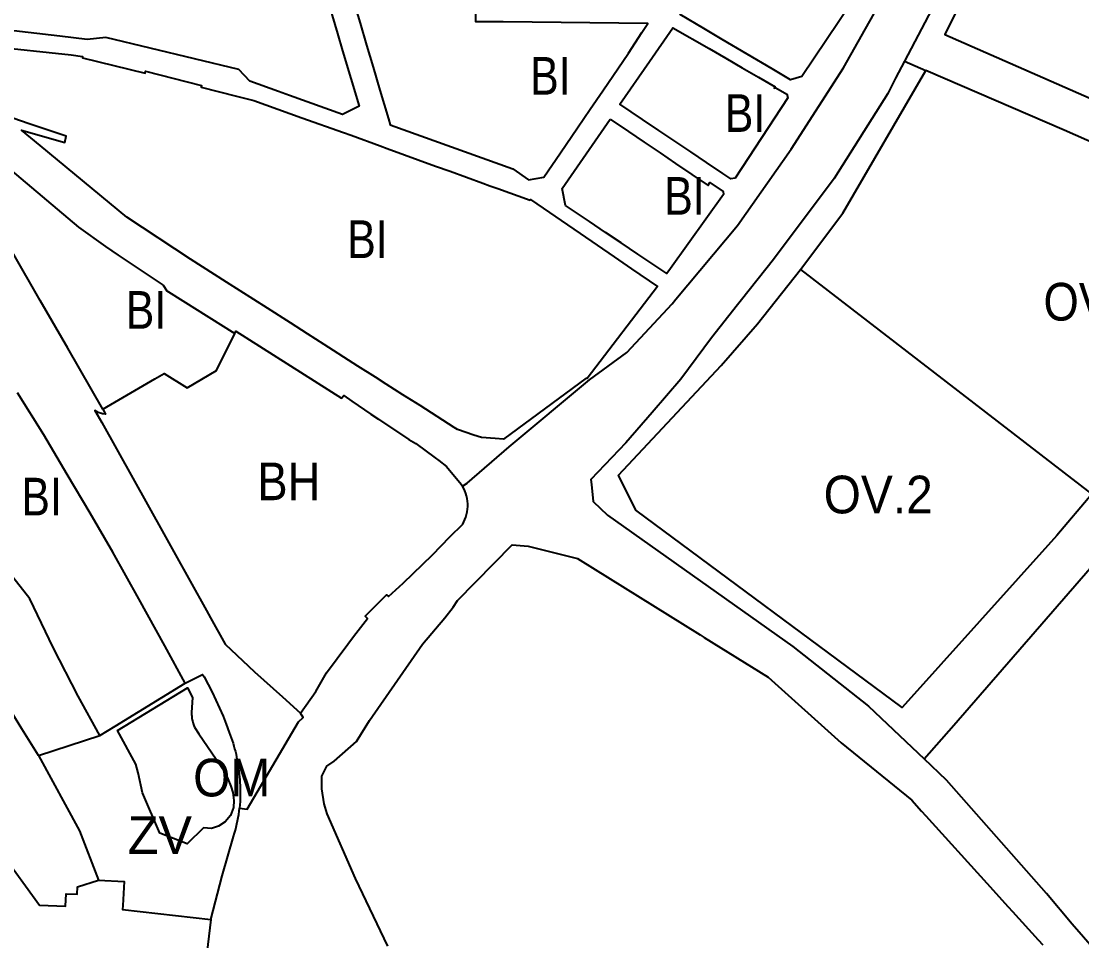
# Model space of a CAD drawing. Extents: x -650451 to -642268, y -1075216 to -1066610.
# Drawn here: x -646568.6 to -646146.5, y -1071706.5 to -1071340.4 of the extents above; entities that cross this region are included whole.
import ezdxf

# ---------------------------------------------------------------- set-up
doc = ezdxf.new("R2010")
doc.units = 0
doc.header["$LTSCALE"] = 6
doc.layers.add('1', color=7, linetype='Continuous', lineweight=35)
doc.layers.add('2', color=7, linetype='Continuous')
doc.layers.add('3', color=7, linetype='Continuous')

msp = doc.modelspace()

# ---------------------------------------------------------------- linework, layer by layer
at = {"layer": '1'}
for p, q in [((-646217.049, -1071356.382), (-646208.577, -1071360.044)), ((-646258.487, -1071439.265), (-646142.584, -1071528.664)), ((-646561.68, -1071632.65), (-646537.28, -1071624.8))]:
    msp.add_line(p, q, dxfattribs=at)
for points in [[(-646392.911, -1071525.561), (-646391.108, -1071524.244), (-646374.45, -1071509.81), (-646342.45, -1071483.12), (-646327.57, -1071472.32), (-646309.6, -1071452.95), (-646308.03, -1071451.08), (-646283.51, -1071421.76), (-646262.18, -1071391.43), (-646241.36, -1071358.97), (-646222.12, -1071324.74), (-646206.54, -1071289.65), (-646193.19, -1071252.61), (-646178.49, -1071182.4), (-646171.94, -1071170.27), (-646172.61, -1071166.36), (-646173.64, -1071160.29), (-646173.49, -1071159.23), (-646173.32, -1071157.96), (-646170.85, -1071151.93)], [(-646063.59, -1071186.331), (-646067.78, -1071184.93), (-646098.16, -1071177.77), (-646109.85, -1071175.02), (-646126.02, -1071172.86), (-646132.63, -1071174.42), (-646136.02, -1071175.37), (-646145.65, -1071182.37), (-646154.59, -1071201.81), (-646173.21, -1071258.81), (-646188.04, -1071296.73), (-646204.83, -1071333.12), (-646217.049, -1071356.382)], [(-646067.097, -1071196.699), (-646132.307, -1071183.438), (-646143.982, -1071201.827), (-646151.834, -1071223.174), (-646162.478, -1071257.888), (-646165.996, -1071267.807), (-646186.109, -1071315.352), (-646201.064, -1071345.678), (-646127.301, -1071378.036)], [(-646452.25, -1071312.89), (-646442.68, -1071345.32), (-646440.65, -1071352.19), (-646434.14, -1071374.25), (-646440.74, -1071377.55), (-646461.86, -1071369.97), (-646466.24, -1071368.39), (-646477.53, -1071364.34), (-646481.95, -1071359.59), (-646517.19, -1071351.18), (-646534.95, -1071346.94), (-646542.32, -1071347.73), (-646553.24, -1071346.43), (-646574.89, -1071343.86)], [(-646439.12, -1071323.11), (-646433.72, -1071341.27), (-646431.13, -1071350.01), (-646428.54, -1071358.71), (-646425.8, -1071367.9), (-646422.43, -1071379.23), (-646421.72, -1071381.63), (-646372.95, -1071399.22), (-646366.71, -1071403.61), (-646360.58, -1071402.51), (-646353.92, -1071392.76), (-646347.17, -1071382.87), (-646342.11, -1071375.46), (-646337.08, -1071368.1), (-646326.88, -1071353.16), (-646321.55, -1071344.91), (-646319.22, -1071341.3), (-646376.74, -1071340.72), (-646387.69, -1071340.72), (-646387.69, -1071331.92)], [(-646581.25, -1071350.31), (-646548.68, -1071353.85), (-646544.12, -1071354.44), (-646544.23, -1071354.96), (-646519.26, -1071361.18), (-646519.06, -1071360.35), (-646496.85, -1071366.04), (-646497.01, -1071366.72), (-646482.94, -1071370.22), (-646475.95, -1071372.05), (-646456.84, -1071378.89), (-646440.29, -1071384.76), (-646437.31, -1071385.84), (-646425.79, -1071390.03), (-646422.97, -1071391.05), (-646403.65, -1071398.07), (-646397.82, -1071400.18), (-646384.85, -1071404.89), (-646382.03, -1071405.91), (-646378.93, -1071407.04), (-646366.05, -1071411.72), (-646365.93, -1071411.37), (-646346.14, -1071424.95), (-646339.37, -1071429.58), (-646332.59, -1071434.24), (-646325.72, -1071438.95), (-646315.42, -1071446.02), (-646343.41, -1071482.71), (-646343.74, -1071482.57), (-646376.59, -1071506.83), (-646379.94, -1071506.59), (-646385.46, -1071506.19), (-646388.5, -1071505.15), (-646394.92, -1071502.97), (-646396.23, -1071502.14), (-646403.11, -1071497.75), (-646409.86, -1071493.44), (-646416.64, -1071489.13), (-646423.34, -1071484.85), (-646427.63, -1071482.12), (-646434.56, -1071477.7), (-646448, -1071469.14), (-646454.64, -1071464.89), (-646461.44, -1071460.52), (-646470.57, -1071454.67), (-646486.82, -1071444.25), (-646501.13, -1071435.17), (-646526.53, -1071418.41), (-646561.07, -1071389.85), (-646568.41, -1071383.81), (-646551.23, -1071388.71), (-646550.7, -1071386.17), (-646565.84, -1071381.21), (-646571.49, -1071379.19)], [(-646217.049, -1071356.382), (-646220.61, -1071363.16), (-646223.77, -1071369.24), (-646245.1, -1071403.04), (-646269.2, -1071435.22), (-646281.99, -1071451.4), (-646283.52, -1071453.34), (-646293.87, -1071466.43), (-646306.14, -1071482.86), (-646317.52, -1071496.12), (-646327.97, -1071508.29), (-646341.88, -1071522.81), (-646341.66, -1071524.87), (-646340.93, -1071531.64), (-646335.3, -1071537.05), (-646261.46, -1071589.38), (-646231.43, -1071613.06), (-646223.928, -1071620.168), (-646209.322, -1071634.004)], [(-646258.487, -1071439.265), (-646241.68, -1071416.887), (-646208.577, -1071360.044)], [(-646132.229, -1071393.179), (-646153.5, -1071383.85), (-646208.577, -1071360.044)], [(-646536.06, -1071494.9), (-646550.03, -1071470.64), (-646561, -1071451.57), (-646593.69, -1071394.81), (-646587.53, -1071387.19), (-646572.96, -1071399.49), (-646545.77, -1071422.43), (-646535.05, -1071430.14), (-646529.94, -1071433.53), (-646512.01, -1071445.44), (-646510.63, -1071447.76), (-646509.94, -1071448.19), (-646504.28, -1071451.75), (-646483.58, -1071464.76)], [(-646209.322, -1071634.004), (-646197.398, -1071620.579), (-646077.593, -1071482.499), (-646044.949, -1071425.333)], [(-646142.584, -1071528.664), (-646156.471, -1071545.166), (-646217.978, -1071613.552), (-646324, -1071535), (-646330.914, -1071521.11), (-646289.976, -1071477.514), (-646275.615, -1071460.886), (-646258.487, -1071439.265)], [(-646536.06, -1071494.9), (-646515.35, -1071482.75), (-646511.72, -1071480.63), (-646502.58, -1071486.42), (-646490.89, -1071479.44), (-646483.58, -1071464.76)], [(-646483.58, -1071464.76), (-646483.107, -1071463.81), (-646441.14, -1071490.5), (-646440.16, -1071489.43), (-646437.01, -1071491.61), (-646429.42, -1071496.8), (-646426.43, -1071498.81), (-646414.36, -1071506.9), (-646411.47, -1071508.58), (-646403.78, -1071514.21), (-646402.38, -1071515.24), (-646399.37, -1071517.73), (-646393.44, -1071524.71), (-646392.911, -1071525.561)], [(-646503.31, -1071603.95), (-646511.47, -1071589.11), (-646521.8, -1071570.34), (-646532.04, -1071551.72), (-646541.14, -1071536.3), (-646550.23, -1071520.88), (-646559.53, -1071505.12), (-646570, -1071488.38)], [(-646536.06, -1071494.9), (-646535.08, -1071496.91), (-646536.26, -1071496.69), (-646537.89, -1071496.17), (-646539.23, -1071495.37), (-646536.45, -1071500.22), (-646511.87, -1071544.47), (-646507.87, -1071551.64), (-646494.85, -1071575.01), (-646493.27, -1071577.93), (-646487.37, -1071588.37), (-646478.18, -1071597.11), (-646475.69, -1071599.42), (-646464.59, -1071609.41), (-646457.49, -1071615.83)], [(-646537.28, -1071624.8), (-646545.89, -1071609.07), (-646555.78, -1071589.66), (-646565.17, -1071570.4), (-646598.63, -1071527.8), (-646609.21, -1071510.98)], [(-646457.49, -1071615.83), (-646451.35, -1071607.3), (-646447.13, -1071599.81), (-646438.62, -1071588.36), (-646436.34, -1071585.29), (-646430.71, -1071578.12), (-646431.67, -1071577.22), (-646423.17, -1071568.77), (-646422.45, -1071569.38), (-646416.52, -1071564.16), (-646404.87, -1071552.83), (-646397.94, -1071545.68), (-646392.89, -1071540.59), (-646392.421, -1071539.705), (-646392.006, -1071538.774), (-646391.649, -1071537.804), (-646391.357, -1071536.799), (-646391.134, -1071535.766), (-646390.982, -1071534.712), (-646390.905, -1071533.645), (-646390.904, -1071532.572), (-646390.979, -1071531.502), (-646391.13, -1071530.442), (-646391.354, -1071529.401), (-646391.649, -1071528.386), (-646392.01, -1071527.404), (-646392.432, -1071526.46), (-646392.911, -1071525.561)], [(-646422.74, -1071708.61), (-646435.53, -1071681.73), (-646446.848, -1071655.933), (-646448, -1071652), (-646449, -1071646), (-646449, -1071641), (-646447, -1071637), (-646444, -1071635), (-646435.08, -1071627.07), (-646429.99, -1071618.76), (-646408.82, -1071588.44), (-646399.95, -1071577.85), (-646396.74, -1071573.64), (-646395.01, -1071571.03), (-646373.15, -1071548.85), (-646366.81, -1071549.42), (-646347.22, -1071554.23), (-646298.46, -1071584.67), (-646296.79, -1071585.71), (-646271.38, -1071601.57), (-646242.35, -1071627.62), (-646214.19, -1071650.52), (-646210.29, -1071654.83), (-646208.56, -1071656.73), (-646184.36, -1071683.46), (-646175.81, -1071692.91), (-646174.08, -1071694.82), (-646163.9, -1071706.08), (-646162.04, -1071708.13)], [(-646561.68, -1071632.65), (-646568.26, -1071622.03), (-646587.29, -1071591.3)], [(-646537.28, -1071624.8), (-646531.2, -1071621.07), (-646503.31, -1071603.95)], [(-646503.31, -1071603.95), (-646496.36, -1071600.42), (-646495.79, -1071601.42), (-646494.143, -1071604.466), (-646492.565, -1071607.552), (-646491.057, -1071610.675), (-646489.622, -1071613.833), (-646488.259, -1071617.023), (-646486.971, -1071620.242), (-646485.758, -1071623.489), (-646484.62, -1071626.76), (-646484.275, -1071627.842), (-646483.948, -1071628.931), (-646483.642, -1071630.028), (-646483.354, -1071631.13), (-646483.087, -1071632.238), (-646482.84, -1071633.351), (-646482.613, -1071634.469), (-646482.406, -1071635.592), (-646482.219, -1071636.717), (-646482.054, -1071637.846), (-646481.908, -1071638.977), (-646481.783, -1071640.11), (-646481.679, -1071641.245), (-646481.595, -1071642.38), (-646481.532, -1071643.515), (-646481.49, -1071644.65), (-646481.429, -1071645.925), (-646481.397, -1071647.203), (-646481.395, -1071648.483), (-646481.421, -1071649.765), (-646481.478, -1071651.047), (-646481.563, -1071652.329), (-646481.679, -1071653.609)], [(-646481.679, -1071653.609), (-646478.668, -1071654.059), (-646458.19, -1071619.33), (-646456.43, -1071617.64), (-646457.49, -1071615.83)], [(-646561.68, -1071632.65), (-646545.319, -1071662.695), (-646537.83, -1071682.37)], [(-645596.405, -1072296.114), (-645664.88, -1072226.59), (-645666.4, -1072225.05), (-645744.42, -1072145.83), (-645770.72, -1072118.71), (-645820.57, -1072067.31), (-645874.53, -1072011.68), (-645883.81, -1072002.11), (-645930.57, -1071954.35), (-645975.01, -1071901.96), (-646003.04, -1071868.9), (-646150.43, -1071699.82), (-646160.52, -1071687.59), (-646200.32, -1071642.53), (-646209.322, -1071634.004)], [(-646493.07, -1071698.02), (-646488.53, -1071680.55), (-646484.02, -1071664.89), (-646483.647, -1071663.67), (-646483.302, -1071662.439), (-646482.984, -1071661.198), (-646482.694, -1071659.949), (-646482.433, -1071658.693), (-646482.201, -1071657.429), (-646481.998, -1071656.16), (-646481.823, -1071654.887), (-646481.679, -1071653.609)], [(-646599.91, -1071676.7), (-646576.23, -1071671.54), (-646561.25, -1071692.22), (-646550.94, -1071692.73), (-646550.69, -1071687.74), (-646546.29, -1071687.96), (-646546.14, -1071684.96), (-646537.83, -1071682.37)], [(-646537.83, -1071682.37), (-646527.65, -1071682.88), (-646528.12, -1071692.36), (-646528.2, -1071694.03), (-646493.07, -1071698.02)], [(-646493.07, -1071698.02), (-646495.05, -1071714.52), (-646496.94, -1071733.76), (-646498.98, -1071753.64), (-646499.22, -1071754.7), (-646503.16, -1071794.13), (-646504.93, -1071812.52), (-646513.09, -1071870.85), (-646514.6, -1071878.48), (-646516.21, -1071888.59), (-646520.43, -1071906.43), (-646526.36, -1071922.76), (-646532.74, -1071938.42), (-646542.34, -1071958.23), (-646549.35, -1071970.07), (-646560.5, -1071985.93), (-646563.366, -1071989.538)]]:
    msp.add_lwpolyline(points, dxfattribs=at)
for points in [[(-646288.2, -1071304.34), (-646280.01, -1071308.05), (-646272.82, -1071311.27), (-646258.36, -1071317.73), (-646251.15, -1071320.96), (-646243.61, -1071324.33), (-646237.95, -1071327.12), (-646236.23, -1071330.04), (-646238.32, -1071333.21), (-646257.93, -1071362.49), (-646262.39, -1071363.73), (-646269.74, -1071359.4), (-646289.66, -1071347.65), (-646296.97, -1071343.34), (-646306.36, -1071337.8)], [(-646318.57, -1071356.51), (-646309.22, -1071343.04), (-646294.81, -1071351.36), (-646288.16, -1071355.19), (-646281.64, -1071358.96), (-646275.12, -1071362.72), (-646268.57, -1071366.5), (-646268.89, -1071367.04), (-646268.23, -1071366.91), (-646263.89, -1071369.47), (-646263.52, -1071370.88), (-646284.45, -1071402.87), (-646286.19, -1071403.21), (-646289.34, -1071401.02), (-646295.82, -1071396.68), (-646302.16, -1071392.4), (-646308.53, -1071388.13), (-646314.84, -1071383.91), (-646321.34, -1071379.56), (-646330.36, -1071373.51)], [(-646334.23, -1071379.38), (-646326.93, -1071384.33), (-646320.62, -1071388.6), (-646314.33, -1071392.86), (-646308.15, -1071397.04), (-646295.25, -1071405.78), (-646294.5, -1071404.68), (-646289.29, -1071408.21), (-646289.15, -1071409.39), (-646310.25, -1071438.85), (-646311.7, -1071440.88), (-646316.82, -1071437.45), (-646323.25, -1071433.12), (-646329.81, -1071428.7), (-646336.02, -1071424.52), (-646342.41, -1071420.21), (-646351.92, -1071413.81), (-646353.27, -1071406.99)], [(-646500.83, -1071615.62), (-646500.793, -1071616.359), (-646500.721, -1071617.099), (-646500.612, -1071617.835), (-646500.468, -1071618.567), (-646500.289, -1071619.291), (-646500.076, -1071620.004), (-646499.829, -1071620.704), (-646499.55, -1071621.39), (-646497.83, -1071624.02), (-646487.56, -1071639.23), (-646486.31, -1071641.97), (-646485.2, -1071644.85), (-646484.38, -1071647.41), (-646483.97, -1071650.63), (-646484.15, -1071653.38), (-646485.29, -1071656.53), (-646487.36, -1071659.1), (-646490.07, -1071660.88), (-646492.89, -1071661.75), (-646496.06, -1071661.5), (-646502.53, -1071667.82), (-646513.43, -1071663.64), (-646520.32, -1071647.59), (-646522, -1071639.62), (-646522.99, -1071636.22), (-646530.27, -1071622.79), (-646502.39, -1071605.72), (-646500.34, -1071609.66)]]:
    msp.add_lwpolyline(points, close=True, dxfattribs=at)

# ---------------------------------------------------------------- texts
at = {"layer": '2'}
for s, width, p in [('BI', 0.85, (-646366.028, -1071369.679)), ('BI', 0.85, (-646288.606, -1071384.496)), ('BI', 0.85, (-646312.685, -1071417.465)), ('BI', 0.85, (-646438.819, -1071434.69)), ('BI', 0.85, (-646526.983, -1071462.843)), ('BH', 0.9, (-646474.59, -1071531.09))]:
    msp.add_text(s, height=15, dxfattribs=dict(at, width=width)).set_placement(p)
msp.add_text('ZV', height=15, dxfattribs=at).set_placement((-646526.208, -1071671.882))
at = {"layer": '3'}
for s, width, p in [('OV.1', 0.9, (-646161.778, -1071459.597)), ('BI', 0.85, (-646568.513, -1071537.162)), ('OV.2', 0.95, (-646249.26, -1071536.329)), ('OM', 0.95, (-646500.141, -1071648.994))]:
    msp.add_text(s, height=15, dxfattribs=dict(at, width=width)).set_placement(p)

doc.saveas('drawing.dxf')
